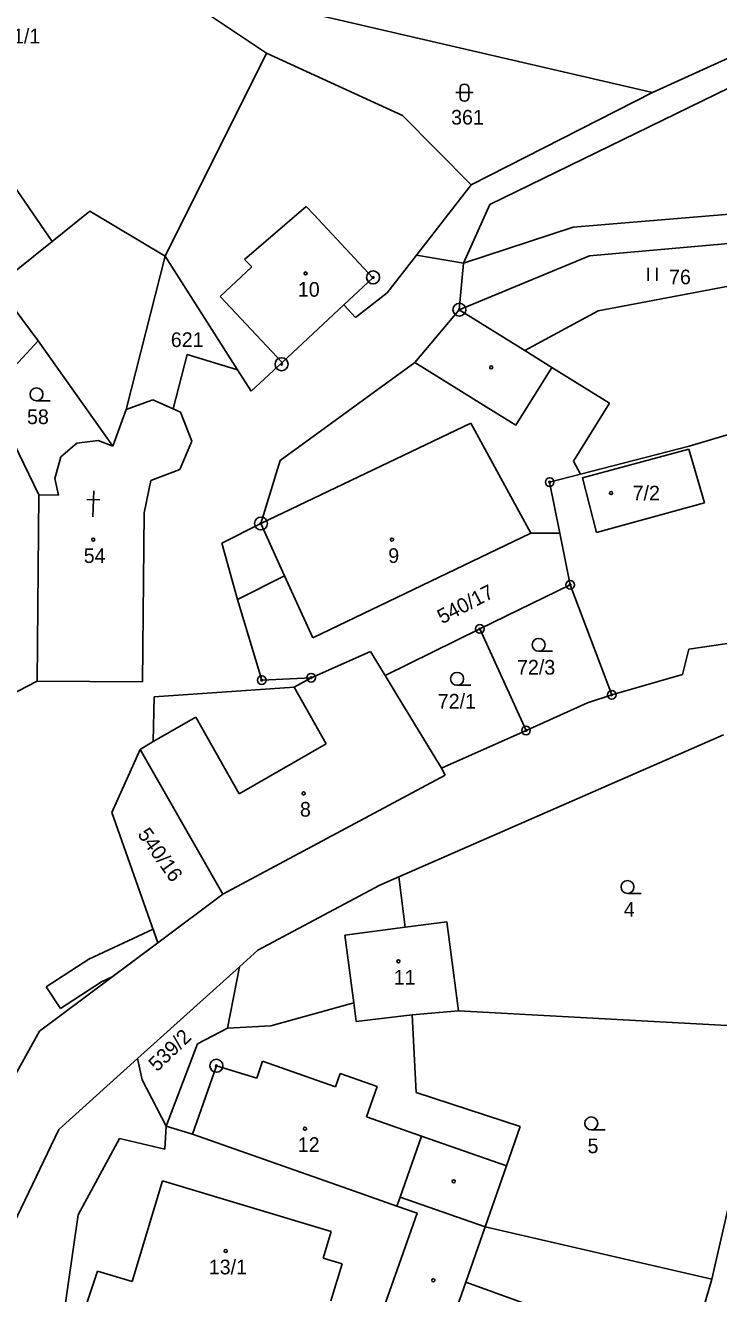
# Model space of a CAD drawing. Extents: x -547623 to -538651, y -1096714 to -1086522.
# Drawn here: x -544759 to -544678.6, y -1094605.9 to -1094458.9 of the extents above; entities that cross this region are included whole.
import ezdxf

# ---------------------------------------------------------------- set-up
doc = ezdxf.new("R2010")
doc.units = 0
for name, color, linetype in [('Vrstva 1', 7, 'Continuous'), ('Vrstva 25', 7, 'Continuous'), ('Vrstva 30', 7, 'Continuous'), ('Vrstva 33', 7, 'Continuous'), ('Vrstva 83', 7, 'Continuous'), ('Vrstva 86', 7, 'Continuous'), ('Vrstva 90', 7, 'Continuous'), ('Vrstva 92', 7, 'Continuous')]:
    doc.layers.add(name, color=color, linetype=linetype)

msp = doc.modelspace()

# ---------------------------------------------------------------- linework, layer by layer
at = {"layer": 'Vrstva 1'}
for points in [[(-544778.45, -1094430.5), (-544731.03, -1094462.14)], [(-544755.87, -1094483.95), (-544786.13, -1094439.82)], [(-544686.29, -1094466.69), (-544660.7, -1094455.03)], [(-544731.52, -1094456.22), (-544686.29, -1094466.69)], [(-544705.17, -1094479.66), (-544660.47, -1094457.87)], [(-544742.77, -1094485.64), (-544731.03, -1094462.14)], [(-544731.03, -1094462.14), (-544715.27, -1094469.34)], [(-544707.33, -1094477.39), (-544686.29, -1094466.69)], [(-544715.27, -1094469.34), (-544707.33, -1094477.39)], [(-544707.33, -1094477.39), (-544713.66, -1094485.53)], [(-544643.93, -1094478), (-544695.48, -1094482.29)], [(-544755.87, -1094483.95), (-544751.48, -1094480.43)], [(-544751.48, -1094480.43), (-544742.77, -1094485.64)], [(-544708.21, -1094486.45), (-544705.17, -1094479.66)], [(-544693.6, -1094485.63), (-544643.93, -1094481.2)], [(-544637.93, -1094481.62), (-544692.61, -1094491.98)], [(-544695.48, -1094482.29), (-544708.21, -1094486.45)], [(-544755.87, -1094483.95), (-544760.19, -1094487.43)], [(-544742.77, -1094485.64), (-544747.29, -1094503.43)], [(-544734.37, -1094498.83), (-544742.77, -1094485.64)], [(-544713.66, -1094485.53), (-544717.06, -1094489.9)], [(-544708.21, -1094486.45), (-544713.66, -1094485.53)], [(-544708.69, -1094491.86), (-544693.6, -1094485.63)], [(-544708.21, -1094486.45), (-544708.69, -1094491.86)], [(-544720.7, -1094492.75), (-544717.06, -1094489.9)], [(-544722.06, -1094491.29), (-544729.22, -1094497.98)], [(-544722.06, -1094491.29), (-544720.7, -1094492.75)], [(-544713.85, -1094497.96), (-544708.69, -1094491.86)], [(-544708.69, -1094491.86), (-544701.08, -1094496.59)], [(-544692.61, -1094491.98), (-544701.08, -1094496.59)], [(-544757.46, -1094495.48), (-544768.89, -1094507.83)], [(-544757.46, -1094495.48), (-544748.84, -1094507.65)], [(-544701.08, -1094496.59), (-544697.95, -1094498.54)], [(-544740.22, -1094497.05), (-544741.83, -1094503.36)], [(-544740.22, -1094497.05), (-544734.37, -1094498.83)], [(-544729.22, -1094497.98), (-544732.79, -1094501.31)], [(-544729.46, -1094509.31), (-544713.85, -1094497.96)], [(-544732.79, -1094501.31), (-544734.37, -1094498.83)], [(-544697.95, -1094498.54), (-544691.27, -1094502.7)], [(-544744.2, -1094502.31), (-544747.29, -1094503.43)], [(-544741.83, -1094503.36), (-544744.2, -1094502.31)], [(-544747.29, -1094503.43), (-544748.84, -1094507.65)], [(-544740.98, -1094503.74), (-544741.83, -1094503.36)], [(-544739.69, -1094507.1), (-544740.98, -1094503.74)], [(-544695.45, -1094509.41), (-544691.27, -1094502.7)], [(-544682.04, -1094507.65), (-544677.13, -1094506.19)], [(-544760.31, -1094507.33), (-544757.39, -1094513.32)], [(-544753.01, -1094507.32), (-544754.84, -1094508.89)], [(-544750.54, -1094507.01), (-544753.01, -1094507.32)], [(-544748.84, -1094507.65), (-544750.54, -1094507.01)], [(-544741.06, -1094510.36), (-544739.69, -1094507.1)], [(-544694.66, -1094510.91), (-544682.04, -1094507.65)], [(-544694.43, -1094511.35), (-544682.08, -1094508)], [(-544682.08, -1094508), (-544680.27, -1094514.25)], [(-544754.84, -1094508.89), (-544755.56, -1094511.42)], [(-544731.67, -1094516.63), (-544729.46, -1094509.31)], [(-544695.45, -1094509.41), (-544694.66, -1094510.91)], [(-544744.43, -1094511.65), (-544741.06, -1094510.36)], [(-544698.22, -1094511.83), (-544694.66, -1094510.91)], [(-544755.56, -1094511.42), (-544755.14, -1094513.33)], [(-544745.21, -1094515.38), (-544744.43, -1094511.65)], [(-544697.04, -1094517.75), (-544698.22, -1094511.83)], [(-544692.78, -1094517.66), (-544694.43, -1094511.35)], [(-544757.59, -1094534.91), (-544757.39, -1094513.32)], [(-544755.14, -1094513.33), (-544757.39, -1094513.32)], [(-544745.4, -1094534.97), (-544745.21, -1094515.38)], [(-544680.27, -1094514.25), (-544692.78, -1094517.66)], [(-544731.67, -1094516.63), (-544736.19, -1094518.9)], [(-544700.41, -1094517.75), (-544725.67, -1094529.86)], [(-544700.41, -1094517.75), (-544697.04, -1094517.75)], [(-544695.85, -1094523.73), (-544697.04, -1094517.75)], [(-544736.19, -1094518.9), (-544734.37, -1094525.42)], [(-544728.92, -1094522.68), (-544734.37, -1094525.42)], [(-544725.67, -1094529.86), (-544728.92, -1094522.68)], [(-544706.32, -1094528.85), (-544695.85, -1094523.73)], [(-544691.03, -1094536.49), (-544695.85, -1094523.73)], [(-544734.37, -1094525.42), (-544731.58, -1094534.78)], [(-544717.29, -1094534.23), (-544706.32, -1094528.85)], [(-544706.32, -1094528.85), (-544700.96, -1094540.61)], [(-544664.25, -1094528.58), (-544682.08, -1094531.21)], [(-544725.85, -1094534.5), (-544718.96, -1094531.48)], [(-544717.29, -1094534.23), (-544718.96, -1094531.48)], [(-544682.82, -1094534.14), (-544682.08, -1094531.21)], [(-544731.58, -1094534.78), (-544725.85, -1094534.5)], [(-544725.85, -1094534.5), (-544727.82, -1094535.59)], [(-544715.92, -1094536.48), (-544717.29, -1094534.23)], [(-544691.03, -1094536.49), (-544682.82, -1094534.14)], [(-544766.29, -1094539.37), (-544757.59, -1094534.91)], [(-544745.4, -1094534.97), (-544757.59, -1094534.91)], [(-544744.05, -1094536.73), (-544727.82, -1094535.59)], [(-544744.05, -1094536.73), (-544744.14, -1094541.91)], [(-544710.88, -1094544.77), (-544715.92, -1094536.48)], [(-544693.85, -1094537.43), (-544700.96, -1094540.61)], [(-544691.03, -1094536.49), (-544693.85, -1094537.43)], [(-544700.96, -1094540.61), (-544710.76, -1094544.98)], [(-544745.67, -1094542.8), (-544744.14, -1094541.91)], [(-544715.7, -1094557.57), (-544678.07, -1094541.11)], [(-544745.67, -1094542.8), (-544748.93, -1094550.12)], [(-544745.67, -1094542.8), (-544736.07, -1094559.6)], [(-544710.76, -1094544.98), (-544710.88, -1094544.77)], [(-544710.34, -1094545.78), (-544710.76, -1094544.98)], [(-544736.07, -1094559.6), (-544710.34, -1094545.78)], [(-544748.93, -1094550.12), (-544743.61, -1094565.22)], [(-544717.9, -1094558.53), (-544715.7, -1094557.57)], [(-544714.95, -1094563.39), (-544715.7, -1094557.57)], [(-544743.61, -1094565.22), (-544736.07, -1094559.6)], [(-544732.04, -1094566.09), (-544717.9, -1094558.53)], [(-544710.13, -1094562.79), (-544714.95, -1094563.39)], [(-544708.79, -1094573.1), (-544710.13, -1094562.79)], [(-544757.33, -1094575.46), (-544743.61, -1094565.22)], [(-544734.17, -1094568.01), (-544732.04, -1094566.09)], [(-544745.95, -1094578.62), (-544734.17, -1094568.01)], [(-544734.17, -1094568.01), (-544735.56, -1094575.12)], [(-544730.52, -1094574.86), (-544720.91, -1094572.16)], [(-544720.91, -1094572.16), (-544720.63, -1094574.34)], [(-544720.63, -1094574.34), (-544714.16, -1094573.58)], [(-544714.16, -1094573.58), (-544708.79, -1094573.1)], [(-544713.69, -1094582.58), (-544714.16, -1094573.58)], [(-544708.79, -1094573.1), (-544672.7, -1094575.08)], [(-544769.76, -1094597.88), (-544757.33, -1094575.46)], [(-544739.03, -1094576.94), (-544735.56, -1094575.12)], [(-544735.56, -1094575.12), (-544730.52, -1094574.86)], [(-544742.63, -1094586.46), (-544739.03, -1094576.94)], [(-544755.08, -1094586.85), (-544745.95, -1094578.62)], [(-544745.43, -1094581.08), (-544745.95, -1094578.62)], [(-544742.63, -1094586.46), (-544745.43, -1094581.08)], [(-544701.62, -1094586.5), (-544713.69, -1094582.58)], [(-544767.78, -1094613.32), (-544755.08, -1094586.85)], [(-544742.82, -1094589.13), (-544742.63, -1094586.46)], [(-544739.61, -1094587.4), (-544742.63, -1094586.46)], [(-544739.61, -1094587.4), (-544721.47, -1094593.77)], [(-544701.62, -1094586.5), (-544703.22, -1094591.07)], [(-544752.84, -1094596.76), (-544748.06, -1094587.91)], [(-544748.06, -1094587.91), (-544742.82, -1094589.13)], [(-544703.22, -1094591.07), (-544705.71, -1094598.15)], [(-544679.43, -1094604.18), (-544676.55, -1094591.57)], [(-544721.47, -1094593.77), (-544715.91, -1094595.72)], [(-544715.55, -1094594.7), (-544715.91, -1094595.72)], [(-544715.55, -1094594.7), (-544705.71, -1094598.15)], [(-544754.6, -1094609.06), (-544752.84, -1094596.76)], [(-544707.95, -1094604.53), (-544705.71, -1094598.15)], [(-544679.43, -1094604.18), (-544705.71, -1094598.15)], [(-544707.95, -1094604.53), (-544711.11, -1094613.53)], [(-544707.95, -1094604.53), (-544694.48, -1094609.43)], [(-544680.66, -1094608.45), (-544679.43, -1094604.18)]]:
    msp.add_lwpolyline(points, dxfattribs=at)
at = {"layer": 'Vrstva 25'}
for p, q in [((-544709.1, -1094466.7), (-544707.1, -1094466.7)), ((-544708.6, -1094467.2), (-544708.6, -1094466.2)), ((-544707.6, -1094466.2), (-544707.6, -1094467.2)), ((-544686.81, -1094488.49), (-544686.81, -1094486.99)), ((-544685.81, -1094488.49), (-544685.81, -1094486.99)), ((-544757.67, -1094502.41), (-544756.07, -1094502.41)), ((-544751.83, -1094513.83), (-544750.33, -1094513.89)), ((-544751.15, -1094515.86), (-544751.04, -1094512.86)), ((-544699.49, -1094531.44), (-544697.89, -1094531.44)), ((-544708.94, -1094535.38), (-544707.34, -1094535.38)), ((-544689.2, -1094559.5), (-544687.6, -1094559.5)), ((-544693.4, -1094586.9), (-544691.8, -1094586.9))]:
    msp.add_line(p, q, dxfattribs=at)
for centre, radius in [((-544726.5, -1094487.65), 0.175), ((-544704.99, -1094498.54), 0.175), ((-544757.67, -1094501.66), 0.75), ((-544691.11, -1094513.1), 0.175), ((-544751.1, -1094518.5), 0.175), ((-544716.49, -1094518.5), 0.175), ((-544699.49, -1094530.69), 0.75), ((-544708.94, -1094534.63), 0.75), ((-544726.72, -1094547.9), 0.175), ((-544689.2, -1094558.75), 0.75), ((-544715.74, -1094567.36), 0.175), ((-544693.4, -1094586.15), 0.75), ((-544726.57, -1094586.76), 0.175), ((-544709.34, -1094592.86), 0.175), ((-544735.75, -1094600.94), 0.175), ((-544711.7, -1094604.33), 0.175)]:
    msp.add_circle(centre, radius, dxfattribs=at)
for centre, start, end in [((-544708.1, -1094466.2), 0, 180), ((-544708.1, -1094467.2), 180, 0)]:
    msp.add_arc(centre, 0.5, start, end, dxfattribs=at)
at = {"layer": 'Vrstva 30'}
for p, q in [((-544751.6, -1094567.13), (-544744.17, -1094563.64)), ((-544756.55, -1094570.34), (-544751.6, -1094567.13)), ((-544750.14, -1094569.75), (-544754.89, -1094572.84)), ((-544748.92, -1094569.18), (-544750.14, -1094569.75)), ((-544754.89, -1094572.84), (-544756.55, -1094570.34))]:
    msp.add_line(p, q, dxfattribs=at)
msp.add_lwpolyline([(-544744.17, -1094563.64), (-544743.61, -1094565.22), (-544748.92, -1094569.18)], dxfattribs=at)
at = {"layer": 'Vrstva 33'}
for points in [[(-544733.56, -1094486.02), (-544726.42, -1094479.89)], [(-544726.42, -1094479.89), (-544725.53, -1094480.84)], [(-544725.53, -1094480.84), (-544718.7, -1094488.15)], [(-544765.97, -1094484.06), (-544757.46, -1094495.48)], [(-544732.74, -1094486.9), (-544733.56, -1094486.02)], [(-544736.39, -1094490.31), (-544732.74, -1094486.9)], [(-544718.7, -1094488.15), (-544722.06, -1094491.29)], [(-544729.22, -1094497.98), (-544736.39, -1094490.31)], [(-544713.85, -1094497.96), (-544705.59, -1094503.1)], [(-544702.13, -1094505.25), (-544697.95, -1094498.54)], [(-544705.59, -1094503.1), (-544702.13, -1094505.25)], [(-544731.67, -1094516.63), (-544707.37, -1094505)], [(-544707.37, -1094505), (-544700.41, -1094517.75)], [(-544728.92, -1094522.68), (-544731.67, -1094516.63)], [(-544727.82, -1094535.59), (-544724.12, -1094542.15)], [(-544744.14, -1094541.91), (-544739.21, -1094539.06)], [(-544739.21, -1094539.06), (-544735.51, -1094545.62)], [(-544734.19, -1094547.97), (-544724.12, -1094542.15)], [(-544735.51, -1094545.62), (-544734.19, -1094547.97)], [(-544721.93, -1094564.32), (-544714.95, -1094563.39)], [(-544721.93, -1094564.32), (-544720.91, -1094572.16)], [(-544736.82, -1094579.47), (-544739.61, -1094587.4)], [(-544736.82, -1094579.47), (-544732.15, -1094580.91)], [(-544732.15, -1094580.91), (-544731.5, -1094578.93)], [(-544731.5, -1094578.93), (-544723.04, -1094581.9)], [(-544722.5, -1094580.38), (-544723.04, -1094581.9)], [(-544722.5, -1094580.38), (-544718.22, -1094581.88)], [(-544718.22, -1094581.88), (-544719.45, -1094585.37)], [(-544719.45, -1094585.37), (-544713.05, -1094587.61)], [(-544715.55, -1094594.7), (-544713.05, -1094587.61)], [(-544713.05, -1094587.61), (-544703.22, -1094591.07)], [(-544746.6, -1094604.47), (-544743.07, -1094592.79)], [(-544743.07, -1094592.79), (-544723.54, -1094598.69)], [(-544713.58, -1094596.54), (-544718.62, -1094610.89)], [(-544715.91, -1094595.72), (-544713.58, -1094596.54)], [(-544723.54, -1094598.69), (-544724.46, -1094601.75)], [(-544724.46, -1094601.75), (-544722.26, -1094602.41)], [(-544722.26, -1094602.41), (-544723.56, -1094606.72)], [(-544752.56, -1094609.19), (-544750.59, -1094603.27)], [(-544750.59, -1094603.27), (-544746.6, -1094604.47)]]:
    msp.add_lwpolyline(points, dxfattribs=at)
at = {"layer": 'Vrstva 83'}
for centre, radius in [((-544718.67, -1094488.11), 0.75), ((-544718.67, -1094488.11), 0.1), ((-544708.68, -1094491.85), 0.75), ((-544708.68, -1094491.85), 0.1), ((-544729.28, -1094498.17), 0.75), ((-544729.28, -1094498.17), 0.1), ((-544698.22, -1094511.83), 0.5), ((-544698.22, -1094511.83), 0.1), ((-544731.66, -1094516.63), 0.75), ((-544731.66, -1094516.63), 0.1), ((-544695.85, -1094523.73), 0.5), ((-544695.85, -1094523.73), 0.1), ((-544706.32, -1094528.85), 0.5), ((-544706.32, -1094528.85), 0.1), ((-544731.58, -1094534.78), 0.5), ((-544731.58, -1094534.78), 0.1), ((-544725.85, -1094534.5), 0.5), ((-544725.85, -1094534.5), 0.1), ((-544691.03, -1094536.49), 0.5), ((-544691.03, -1094536.49), 0.1), ((-544700.96, -1094540.61), 0.5), ((-544700.96, -1094540.61), 0.1), ((-544736.83, -1094579.47), 0.75), ((-544736.83, -1094579.47), 0.1)]:
    msp.add_circle(centre, radius, dxfattribs=at)
at = {"layer": 'Vrstva 90'}
for points in [[(-544733.56, -1094486.02), (-544726.42, -1094479.89)], [(-544726.42, -1094479.89), (-544725.53, -1094480.84)], [(-544725.53, -1094480.84), (-544718.7, -1094488.15)], [(-544732.74, -1094486.9), (-544733.56, -1094486.02)], [(-544736.39, -1094490.31), (-544732.74, -1094486.9)], [(-544718.7, -1094488.15), (-544722.06, -1094491.29)], [(-544729.22, -1094497.98), (-544736.39, -1094490.31)], [(-544722.06, -1094491.29), (-544729.22, -1094497.98)], [(-544744.2, -1094502.31), (-544747.29, -1094503.43)], [(-544741.83, -1094503.36), (-544744.2, -1094502.31)], [(-544747.29, -1094503.43), (-544748.84, -1094507.65)], [(-544740.98, -1094503.74), (-544741.83, -1094503.36)], [(-544739.69, -1094507.1), (-544740.98, -1094503.74)], [(-544731.67, -1094516.63), (-544707.37, -1094505)], [(-544707.37, -1094505), (-544700.41, -1094517.75)], [(-544753.01, -1094507.32), (-544754.84, -1094508.89)], [(-544750.54, -1094507.01), (-544753.01, -1094507.32)], [(-544748.84, -1094507.65), (-544750.54, -1094507.01)], [(-544741.06, -1094510.36), (-544739.69, -1094507.1)], [(-544694.43, -1094511.35), (-544682.08, -1094508)], [(-544682.08, -1094508), (-544680.27, -1094514.25)], [(-544754.84, -1094508.89), (-544755.56, -1094511.42)], [(-544744.43, -1094511.65), (-544741.06, -1094510.36)], [(-544755.56, -1094511.42), (-544755.14, -1094513.33)], [(-544745.21, -1094515.38), (-544744.43, -1094511.65)], [(-544692.78, -1094517.66), (-544694.43, -1094511.35)], [(-544757.59, -1094534.91), (-544757.39, -1094513.32)], [(-544755.14, -1094513.33), (-544757.39, -1094513.32)], [(-544745.4, -1094534.97), (-544745.21, -1094515.38)], [(-544680.27, -1094514.25), (-544692.78, -1094517.66)], [(-544728.92, -1094522.68), (-544731.67, -1094516.63)], [(-544700.41, -1094517.75), (-544725.67, -1094529.86)], [(-544725.67, -1094529.86), (-544728.92, -1094522.68)], [(-544725.85, -1094534.5), (-544718.96, -1094531.48)], [(-544717.29, -1094534.23), (-544718.96, -1094531.48)], [(-544725.85, -1094534.5), (-544727.82, -1094535.59)], [(-544715.92, -1094536.48), (-544717.29, -1094534.23)], [(-544745.4, -1094534.97), (-544757.59, -1094534.91)], [(-544727.82, -1094535.59), (-544724.12, -1094542.15)], [(-544710.88, -1094544.77), (-544715.92, -1094536.48)], [(-544744.14, -1094541.91), (-544739.21, -1094539.06)], [(-544739.21, -1094539.06), (-544735.51, -1094545.62)], [(-544745.67, -1094542.8), (-544744.14, -1094541.91)], [(-544734.19, -1094547.97), (-544724.12, -1094542.15)], [(-544745.67, -1094542.8), (-544736.07, -1094559.6)], [(-544710.76, -1094544.98), (-544710.88, -1094544.77)], [(-544710.34, -1094545.78), (-544710.76, -1094544.98)], [(-544736.07, -1094559.6), (-544710.34, -1094545.78)], [(-544735.51, -1094545.62), (-544734.19, -1094547.97)], [(-544721.93, -1094564.32), (-544714.95, -1094563.39)], [(-544710.13, -1094562.79), (-544714.95, -1094563.39)], [(-544708.79, -1094573.1), (-544710.13, -1094562.79)], [(-544721.93, -1094564.32), (-544720.91, -1094572.16)], [(-544720.91, -1094572.16), (-544720.63, -1094574.34)], [(-544720.63, -1094574.34), (-544714.16, -1094573.58)], [(-544714.16, -1094573.58), (-544708.79, -1094573.1)], [(-544736.82, -1094579.47), (-544739.61, -1094587.4)], [(-544736.82, -1094579.47), (-544732.15, -1094580.91)], [(-544732.15, -1094580.91), (-544731.5, -1094578.93)], [(-544731.5, -1094578.93), (-544723.04, -1094581.9)], [(-544722.5, -1094580.38), (-544723.04, -1094581.9)], [(-544722.5, -1094580.38), (-544718.22, -1094581.88)], [(-544718.22, -1094581.88), (-544719.45, -1094585.37)], [(-544719.45, -1094585.37), (-544713.05, -1094587.61)], [(-544739.61, -1094587.4), (-544721.47, -1094593.77)], [(-544715.55, -1094594.7), (-544713.05, -1094587.61)], [(-544746.6, -1094604.47), (-544743.07, -1094592.79)], [(-544743.07, -1094592.79), (-544723.54, -1094598.69)], [(-544721.47, -1094593.77), (-544715.91, -1094595.72)], [(-544715.55, -1094594.7), (-544715.91, -1094595.72)], [(-544723.54, -1094598.69), (-544724.46, -1094601.75)], [(-544724.46, -1094601.75), (-544722.26, -1094602.41)], [(-544722.26, -1094602.41), (-544723.56, -1094606.72)], [(-544752.56, -1094609.19), (-544750.59, -1094603.27)], [(-544750.59, -1094603.27), (-544746.6, -1094604.47)]]:
    msp.add_lwpolyline(points, dxfattribs=at)

# ---------------------------------------------------------------- texts
at = {"layer": 'Vrstva 86'}
for s, p in [('71/1', (-544761.66, -1094461)), ('361', (-544709.64, -1094470.4)), ('76', (-544684.39, -1094488.91)), ('621', (-544742.11, -1094496.18)), ('58', (-544758.77, -1094505.11)), ('72/3', (-544702, -1094534.14)), ('72/1', (-544711.18, -1094538.08)), ('4', (-544689.63, -1094562.2)), ('5', (-544693.83, -1094589.6))]:
    msp.add_text(s, height=1.7, dxfattribs=at).set_placement(p)
for s, rotation, p in [('540/17', 27.394, (-544710.68, -1094528.32)), ('540/16', 305.304, (-544746.03, -1094552.65)), ('539/2', 43.8871, (-544743.7, -1094580.24))]:
    msp.add_text(s, height=1.7, rotation=rotation, dxfattribs=at).set_placement(p)
at = {"layer": 'Vrstva 92'}
for s, p in [('10', (-544727.39, -1094490.35)), ('7/2', (-544688.61, -1094513.95)), ('54', (-544752.2, -1094521.2)), ('9', (-544716.92, -1094521.2)), ('8', (-544727.15, -1094550.6)), ('11', (-544716.29, -1094570.06)), ('12', (-544727.4, -1094589.46)), ('13/1', (-544737.71, -1094603.64))]:
    msp.add_text(s, height=1.7, dxfattribs=at).set_placement(p)

doc.saveas('drawing.dxf')
